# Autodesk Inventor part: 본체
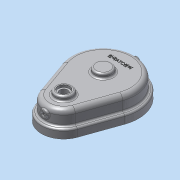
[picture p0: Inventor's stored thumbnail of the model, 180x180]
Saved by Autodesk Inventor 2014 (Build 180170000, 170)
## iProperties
Created: 2024-05
Part Number: 본체
Material: 알루미늄 6061
Document SubType Name: Modeling
Designer: dg
Density: 2.71 g/cm^3
Appearance: 알루미늄 - 평지
Mass: 509.144 g
Surface Area: 646.283 cm^2
Volume: 187.876 cm^3
Author: dg
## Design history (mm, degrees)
sketch "스케치1"
  geometry: L1 (-58.454, -20.667)-(-36.77, -82); L2 (58.454, -20.667)-(36.77, -82); A1 r 62 centre (0, 0) between (-58.454, -20.667) and (58.454, -20.667); A2 r 39 centre (0, -69) between (-36.77, -82) and (36.77, -82); 1 further point
  constraints: 4 end point, 4 point on circle, 4 tangent, 2 centre point, 1 coincident, 1 vertical alignment
  dimensions: "d0" = 124 diameter of A1; "d1" = 78 diameter of A2; "d2" = 69 distance of A2.centre point (0, 0)
extrude "돌출1" new body sketch "스케치1" distance "d3" = 15; taper "d4" = 0 deg
sketch "스케치2"
  geometry: L1 (52.797, -18.667)-(31.113, -80); L2 (-52.797, -18.667)-(-31.113, -80); A1 r 62 centre (0, 0) between (58.454, -20.667) and (-58.454, -20.667) reference; A2 r 39 centre (0, -69) between (-36.77, -82) and (36.77, -82) reference; A3 r 56 centre (0, 0) between (52.797, -18.667) and (-52.797, -18.667); A4 r 33 centre (0, -69) between (-31.113, -80) and (31.113, -80)
  constraints: 4 end point, 4 point on circle, 4 tangent, 2 centre point, 2 coincident
  dimensions: "d5" = 112 diameter of A3; "d6" = 66 diameter of A4
extrude "돌출2" join sketch "스케치2" distance "d7" = 25; taper "d8" = 0 deg
sketch "스케치3"
  geometry: C1 r 15 at (0, 0); A1 r 56 centre (0, 0) between (52.797, -18.667) and (-52.797, -18.667) reference
  constraints: 1 centre point, 1 coincident
  dimensions: "d9" = 30 diameter of C1
extrude "돌출3" join sketch "스케치3" distance "d10" = 8; taper "d11" = 0 deg
sketch "스케치4"
  geometry: C1 r 15 at (0, -69); A1 r 33 centre (0, -69) between (-31.113, -80) and (31.113, -80) reference
  constraints: 1 centre point, 1 coincident
  dimensions: "d12" = 30 diameter of C1
extrude "돌출4" join sketch "스케치4" distance "d13" = 8; taper "d14" = 0 deg
sketch "스케치5"
  geometry: L1 (48.083, -17)-(26.399, -78.333); L2 (-48.083, -17)-(-26.399, -78.333); A1 r 39 centre (0, -69) between (-36.77, -82) and (36.77, -82) reference; A2 r 62 centre (0, 0) between (58.454, -20.667) and (-58.454, -20.667) reference; A3 r 51 centre (0, 0) between (48.083, -17) and (-48.083, -17); A4 r 28 centre (0, -69) between (-26.399, -78.333) and (26.399, -78.333)
  constraints: 4 end point, 4 point on circle, 4 tangent, 2 centre point, 2 coincident
  dimensions: "d15" = 102 diameter of A3; "d16" = 56 diameter of A4
extrude "돌출5" cut sketch "스케치5" distance "d17" = 35; taper "d18" = 0 deg
sketch "스케치6"
  geometry: C1 r 14 at (0, 0); A1 r 51 centre (0, 0) between (48.083, -17) and (-48.083, -17) reference
  constraints: 1 centre point, 1 coincident
  dimensions: "d19" = 28 diameter of C1
extrude "돌출6" join sketch "스케치6" distance "d20" = 8; taper "d21" = 0 deg
sketch "스케치7"
  geometry: C1 r 14 at (0, -69); A1 r 28 centre (0, -69) between (-26.399, -78.333) and (26.399, -78.333) reference
  constraints: 1 centre point, 1 coincident
  dimensions: "d22" = 28 diameter of C1
extrude "돌출7" join sketch "스케치7" distance "d23" = 8; taper "d24" = 0 deg
hole "구멍1" diameter "d27" = 14; stored, may be unused: countersink angle "d31" = 90 deg, drill point angle "d33" = 0 deg; dims "d25" = 10, "d26" = 10, "d28" = 6, "d29" = 20, "d30" = 4.2, "d32" = 8
hole "구멍2" diameter "d36" = 14; stored, may be unused: countersink angle "d40" = 90 deg, drill point angle "d42" = 0 deg; dims "d34" = 10, "d35" = 10, "d37" = 6, "d38" = 20, "d39" = 4.2, "d41" = 10
sketch "스케치8"
  geometry: L1 (-18.667, 15)-(-18.667, 15) reference; L2 (-18.667, 15)-(-18.667, 40) reference; L3 (-18.667, 40)-(-18.667, 40) reference; L4 (-18.667, 15)-(-18.667, 40) reference; L5 (7, 27)-(-7, 27) reference; L6 (-7, 37)-(7, 37) reference; L7 (0, 39.309)-(4, 37); L8 (-4, 37)-(0, 39.309); L9 (0, 39.309)-(0, 37); 1 further point
  constraints: 6 end point, 2 point on line, 1 equal length, 1 midpoint, 1 perpendicular, 1 vertical alignment
  dimensions: "d45" = 8 distance of L7.end L8.start; "d46" = 120 deg angle of L8 L7
revolve "회전1" sketch "스케치8" stored, may be unused: angle "d47" = 90 deg
node "작업 평면1"
sketch "스케치9"
  geometry: L1 (56, 40)-(-56, 40) reference; L2 (62, 0)-(-62, 0) reference; C1 r 6 at (0, 28); 6 further points
  constraints: 1 centre point, 1 midpoint, 1 vertical alignment
  dimensions: "d49" = 12 diameter of C1; "d50" = 28 distance from line of L2 C1.centre
extrude "돌출8" join sketch "스케치9" stored distance "d51" = 8; taper "d52" = 0 deg
hole "구멍3" diameter "d55" = 5.188; stored, may be unused: countersink angle "d59" = 90 deg, drill point angle "d61" = 0 deg; dims "d56" = 100, "d57" = 7, "d58" = 2, "d60" = 10, "d64" = 10, "d65" = 10
node "작업 평면2"
sketch "스케치10"
  geometry: L1 (31.113, 40)-(-31.113, 40) reference; L2 (36.77, 0)-(-36.77, 0) reference; C1 r 6 at (0, 28); 2 further points
  constraints: 1 centre point, 1 midpoint, 1 vertical alignment
  dimensions: "d63" = 12 diameter of C1; "d66" = 28 distance from line of L2 C1.centre
extrude "돌출9" join sketch "스케치10" stored distance "d67" = 8; taper "d68" = 0 deg
hole "구멍4" diameter "d71" = 5.188; stored, may be unused: countersink angle "d75" = 90 deg, drill point angle "d77" = 0 deg; dims "d72" = 15, "d73" = 7, "d74" = 2, "d76" = 10, "d78" = 10, "d79" = 10
sketch "스케치11"
  geometry: L1 (52.797, -18.667)-(31.113, -80); L2 (-52.797, -18.667)-(-30.561, -81.56); L3 (0, 0)-(39.598, 39.598); L4 (0, 0)-(0, 56); A1 r 28 centre (0, -69) between (-26.399, -78.333) and (26.399, -78.333) reference; A2 r 51 centre (0, 0) between (48.083, -17) and (-48.083, -17) reference; A3 r 39 centre (0, -69) between (-36.77, -82) and (36.77, -82) reference; A4 r 62 centre (0, 0) between (58.454, -20.667) and (-58.454, -20.667) reference; A5 r 56 centre (0, 0) between (52.797, -18.667) and (-52.797, -18.667); A6 r 33 centre (0, -69) between (-31.113, -80) and (31.113, -80); 8 further points
  constraints: 8 end point, 8 point on circle, 4 symmetric about line, 4 tangent, 3 point on line, 2 centre point, 2 horizontal alignment, 1 coincident, 1 concentric, 1 vertical
  dimensions: "d80" = 112 diameter of A5; "d81" = 66 diameter of A6; "d82" = 34 vertical distance of point (56, 0) point (47.376, -34); "d83" = 45 deg angle of L4 L3
hole "구멍5" sketch "스케치11" at (56, 0), (35.002, -69), (47.376, -34), (0, -102), (0, 56), (-56, 0), (-47.376, -34), (-35.002, -69), (39.598, 39.598), (-39.598, 39.598) diameter "d84" = 3.242; stored, may be unused: countersink angle "d88" = 90 deg, drill point angle "d90" = 118 deg; dims "d85" = 8, "d86" = 7, "d87" = 2, "d89" = 10
fillet "모깎기1" dims "d91" = 3
fillet "모깎기2" dims "d92" = 3
fillet "모깎기3" dims "d93" = 8
fillet "모깎기4" dims "d94" = 3
fillet "모깎기5" dims "d95" = 3
fillet "모깎기6" dims "d96" = 3
fillet "모깎기7" dims "d97" = 3
fillet "모깎기8" dims "d98" = 3
chamfer "모따기1" distance "d99" = 1; stored, may be unused: second distance "d100" = 2, angle "d101" = 45 deg
sketch "스케치12"
  geometry: L1 (-79, 48)-(-59, 48) reference; L2 (-59, 43.8)-(-79, 43.8) reference; L3 (-54, 45)-(-84, 45) reference; L4 (-81, 48)-(-57, 48) reference; L5 (-79, 47.6)-(-79.231, 48); L6 (-79, 43.8)-(-79, 48) reference; L7 (-69, 48)-(-69, 42.459); L8 (-79.231, 48)-(-79, 48); L9 (-79, 47.6)-(-79, 48); 1 further point
  constraints: 8 end point, 2 collinear, 2 point on line, 1 midpoint, 1 perpendicular
  dimensions: "d102" = 0.4 distance from line of L4 L5.start; "d103" = 30 deg angle of L6 L5
revolve "회전2" sketch "스케치12" stored, may be unused: angle "d104" = 90 deg
sketch "스케치13"
  geometry: C1 r 18 at (0, 0) reference; 1 further point
  constraints: 1 vertical alignment, 1 other
  dimensions: "d105" = 30 distance of C1.centre point (0, 30)
feature "엠보싱1" sketch "스케치13" dims "d0" = 124, "d1" = 78, "d2" = 69, "d106" = 0.5, "d107" = 0
fillet "모깎기9" dims "d108" = 0.1
node "솔리드1"
node "투영된 루프1"
node "투영된 루프2"
node "투영된 루프3"
node "투영된 루프4"
other parameters: "d48" = 59, "d62" = -105
